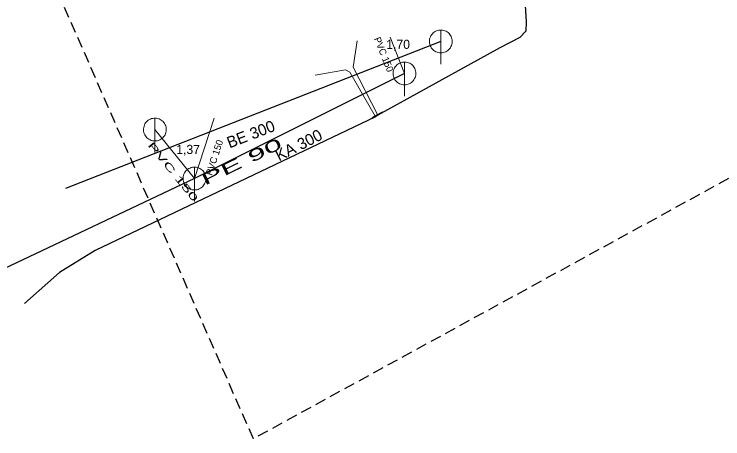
# Model space of a CAD drawing. Extents: x -693324 to -693034, y -967499 to -967236.
# Drawn here: x -693289.5 to -693227.3, y -967499.4 to -967462.2 of the extents above; entities that cross this region are included whole.
import ezdxf

# ---------------------------------------------------------------- set-up
doc = ezdxf.new("R2010")
doc.units = 0
doc.header["$LTSCALE"] = 0.32
doc.linetypes.add('MEDIUM_DASHED', pattern=[4.5, 3, -1.5])
doc.layers.add('1', color=7, linetype='Continuous')
for name, color, linetype, lineweight in [('11', 7, 'Continuous', 13), ('13', 7, 'Continuous', 13), ('14', 7, 'Continuous', 13), ('17', 7, 'Continuous', 25), ('22', 7, 'Continuous', 13), ('34', 7, 'Continuous', 13), ('63', 7, 'MEDIUM_DASHED', 25)]:
    doc.layers.add(name, color=color, linetype=linetype, lineweight=lineweight)

msp = doc.modelspace()

# ---------------------------------------------------------------- linework, layer by layer
at = {"layer": '11'}
for p, q in [((-693256.48, -967464.162), (-693255.221, -967467.353)), ((-693271.923, -967471.278), (-693273.644, -967476.568)), ((-693277.114, -967472.274), (-693273.644, -967476.568))]:
    msp.add_line(p, q, dxfattribs=at)
at = {"layer": '13'}
for points in [[(-693257.581, -967470.955), (-693259.737, -967466.818), (-693259.377, -967464.487)], [(-693257.793, -967471.099), (-693260.022, -967467.23), (-693260.386, -967467.035), (-693263.063, -967467.511)]]:
    msp.add_lwpolyline(points, dxfattribs=at)
at = {"layer": '14', "lineweight": 25}
for p, q in [((-693252.032, -967464.546), (-693284.967, -967477.43)), ((-693255.221, -967467.353), (-693273.644, -967476.568)), ((-693273.644, -967476.568), (-693294.817, -967486.566))]:
    msp.add_line(p, q, dxfattribs=at)
at = {"layer": '14'}
for p, q in [((-693257.767, -967471.145), (-693257.793, -967471.099)), ((-693257.557, -967471.002), (-693257.581, -967470.955))]:
    msp.add_line(p, q, dxfattribs=at)
at = {"layer": '17'}
msp.add_lwpolyline([(-693247.245, -967444.625), (-693244.666, -967460.901), (-693244.541, -967462.822), (-693244.585, -967463.638), (-693245.103, -967464.195), (-693246.853, -967465.098), (-693257.557, -967471.002), (-693257.767, -967471.145), (-693282.342, -967482.884), (-693285.493, -967484.813), (-693288.565, -967487.522)], dxfattribs=at)
at = {"layer": '22'}
for p, q in [((-693252.032, -967466.546), (-693252.031, -967463.546)), ((-693255.221, -967469.353), (-693255.22, -967466.353)), ((-693277.114, -967474.274), (-693277.113, -967471.274)), ((-693273.644, -967478.568), (-693273.643, -967475.568))]:
    msp.add_line(p, q, dxfattribs=at)
for points in [[(-693251.032, -967464.546), (-693251.037, -967464.437), (-693251.055, -967464.329), (-693251.085, -967464.223), (-693251.125, -967464.122), (-693251.177, -967464.025), (-693251.239, -967463.935), (-693251.311, -967463.852), (-693251.391, -967463.778), (-693251.479, -967463.712), (-693251.573, -967463.657), (-693251.673, -967463.612), (-693251.778, -967463.579), (-693251.885, -967463.557), (-693251.994, -967463.547), (-693252.104, -967463.549), (-693252.212, -967463.563), (-693252.319, -967463.588), (-693252.422, -967463.625), (-693252.52, -967463.674), (-693252.612, -967463.732), (-693252.698, -967463.801), (-693252.775, -967463.878), (-693252.844, -967463.964), (-693252.903, -967464.056), (-693252.951, -967464.154), (-693252.988, -967464.257), (-693253.014, -967464.364), (-693253.028, -967464.472), (-693253.031, -967464.582), (-693253.021, -967464.691), (-693253, -967464.798), (-693252.966, -967464.902), (-693252.922, -967465.002), (-693252.867, -967465.097), (-693252.801, -967465.185), (-693252.727, -967465.265), (-693252.644, -967465.337), (-693252.554, -967465.399), (-693252.458, -967465.451), (-693252.356, -967465.492), (-693252.251, -967465.522), (-693252.143, -967465.54), (-693252.033, -967465.546), (-693251.924, -967465.54), (-693251.816, -967465.522), (-693251.711, -967465.493), (-693251.609, -967465.452), (-693251.512, -967465.4), (-693251.422, -967465.338), (-693251.339, -967465.267), (-693251.264, -967465.187), (-693251.199, -967465.099), (-693251.143, -967465.005), (-693251.099, -967464.905), (-693251.065, -967464.801), (-693251.043, -967464.693), (-693251.033, -967464.584)], [(-693254.221, -967467.353), (-693254.226, -967467.244), (-693254.244, -967467.136), (-693254.274, -967467.03), (-693254.314, -967466.929), (-693254.366, -967466.832), (-693254.428, -967466.742), (-693254.5, -967466.659), (-693254.58, -967466.585), (-693254.668, -967466.519), (-693254.762, -967466.464), (-693254.862, -967466.419), (-693254.967, -967466.386), (-693255.074, -967466.364), (-693255.183, -967466.354), (-693255.293, -967466.356), (-693255.401, -967466.37), (-693255.508, -967466.395), (-693255.611, -967466.432), (-693255.709, -967466.481), (-693255.801, -967466.539), (-693255.887, -967466.608), (-693255.964, -967466.685), (-693256.033, -967466.771), (-693256.092, -967466.863), (-693256.14, -967466.961), (-693256.177, -967467.064), (-693256.203, -967467.171), (-693256.217, -967467.279), (-693256.22, -967467.389), (-693256.21, -967467.498), (-693256.189, -967467.605), (-693256.155, -967467.709), (-693256.111, -967467.809), (-693256.056, -967467.904), (-693255.99, -967467.992), (-693255.916, -967468.072), (-693255.833, -967468.144), (-693255.743, -967468.206), (-693255.647, -967468.258), (-693255.545, -967468.299), (-693255.44, -967468.329), (-693255.332, -967468.347), (-693255.222, -967468.353), (-693255.113, -967468.347), (-693255.005, -967468.329), (-693254.9, -967468.3), (-693254.798, -967468.259), (-693254.701, -967468.207), (-693254.611, -967468.145), (-693254.528, -967468.074), (-693254.453, -967467.994), (-693254.388, -967467.906), (-693254.332, -967467.812), (-693254.288, -967467.712), (-693254.254, -967467.608), (-693254.232, -967467.5), (-693254.222, -967467.391)], [(-693276.114, -967472.274), (-693276.119, -967472.165), (-693276.137, -967472.057), (-693276.167, -967471.951), (-693276.207, -967471.85), (-693276.259, -967471.753), (-693276.321, -967471.663), (-693276.393, -967471.58), (-693276.473, -967471.506), (-693276.561, -967471.44), (-693276.655, -967471.385), (-693276.755, -967471.34), (-693276.86, -967471.307), (-693276.967, -967471.285), (-693277.076, -967471.275), (-693277.186, -967471.277), (-693277.294, -967471.291), (-693277.401, -967471.316), (-693277.504, -967471.353), (-693277.602, -967471.402), (-693277.694, -967471.46), (-693277.78, -967471.529), (-693277.857, -967471.606), (-693277.926, -967471.692), (-693277.985, -967471.784), (-693278.033, -967471.882), (-693278.07, -967471.985), (-693278.096, -967472.092), (-693278.11, -967472.2), (-693278.113, -967472.31), (-693278.103, -967472.419), (-693278.082, -967472.526), (-693278.048, -967472.63), (-693278.004, -967472.73), (-693277.949, -967472.825), (-693277.883, -967472.913), (-693277.809, -967472.993), (-693277.726, -967473.065), (-693277.636, -967473.127), (-693277.54, -967473.179), (-693277.438, -967473.22), (-693277.333, -967473.25), (-693277.225, -967473.268), (-693277.115, -967473.274), (-693277.006, -967473.268), (-693276.898, -967473.25), (-693276.793, -967473.221), (-693276.691, -967473.18), (-693276.594, -967473.128), (-693276.504, -967473.066), (-693276.421, -967472.995), (-693276.346, -967472.915), (-693276.281, -967472.827), (-693276.225, -967472.733), (-693276.181, -967472.633), (-693276.147, -967472.529), (-693276.125, -967472.421), (-693276.115, -967472.312)], [(-693272.644, -967476.568), (-693272.649, -967476.459), (-693272.667, -967476.351), (-693272.697, -967476.245), (-693272.737, -967476.144), (-693272.789, -967476.047), (-693272.851, -967475.957), (-693272.923, -967475.874), (-693273.003, -967475.8), (-693273.091, -967475.734), (-693273.185, -967475.679), (-693273.285, -967475.634), (-693273.39, -967475.601), (-693273.497, -967475.579), (-693273.606, -967475.569), (-693273.716, -967475.571), (-693273.824, -967475.585), (-693273.931, -967475.61), (-693274.034, -967475.647), (-693274.132, -967475.696), (-693274.224, -967475.754), (-693274.31, -967475.823), (-693274.387, -967475.9), (-693274.456, -967475.986), (-693274.515, -967476.078), (-693274.563, -967476.176), (-693274.6, -967476.279), (-693274.626, -967476.386), (-693274.64, -967476.494), (-693274.643, -967476.604), (-693274.633, -967476.713), (-693274.612, -967476.82), (-693274.578, -967476.924), (-693274.534, -967477.024), (-693274.479, -967477.119), (-693274.413, -967477.207), (-693274.339, -967477.287), (-693274.256, -967477.359), (-693274.166, -967477.421), (-693274.07, -967477.473), (-693273.968, -967477.514), (-693273.863, -967477.544), (-693273.755, -967477.562), (-693273.645, -967477.568), (-693273.536, -967477.562), (-693273.428, -967477.544), (-693273.323, -967477.515), (-693273.221, -967477.474), (-693273.124, -967477.422), (-693273.034, -967477.36), (-693272.951, -967477.289), (-693272.876, -967477.209), (-693272.811, -967477.121), (-693272.755, -967477.027), (-693272.711, -967476.927), (-693272.677, -967476.823), (-693272.655, -967476.715), (-693272.645, -967476.606)]]:
    msp.add_lwpolyline(points, close=True, dxfattribs=at)
at = {"layer": '34'}
for p, q in [((-693258.225, -967471.349), (-693257.359, -967470.849)), ((-693258.024, -967471.186), (-693257.137, -967470.724))]:
    msp.add_line(p, q, dxfattribs=at)
at = {"layer": '63'}
msp.add_lwpolyline([(-693215.442, -967470.355), (-693268.475, -967499.384), (-693268.475, -967499.384), (-693301.969, -967422.904), (-693301.969, -967422.904), (-693282.431, -967353.124), (-693282.431, -967353.124), (-693315.367, -967297.3), (-693315.367, -967297.3), (-693271.824, -967262.689), (-693271.824, -967262.689), (-693150.127, -967236.451), (-693150.127, -967236.451), (-693034.013, -967255.99), (-693034.013, -967255.99), (-693048.527, -967323.537), (-693048.527, -967323.537), (-693120.541, -967319.63), (-693120.541, -967319.63), (-693193.67, -967351.449), (-693193.67, -967351.449), (-693214.325, -967418.997), (-693214.325, -967418.997)], close=True, dxfattribs=at)

# ---------------------------------------------------------------- texts
at = {"layer": '1'}
for s, height, rotation, p in [('PVC 150 ', 0.6, 292, (-693257.915, -967464.313)), ('BE 300', 1, 21, (-693270.569, -967473.929)), ('KA 300', 1, 27, (-693266.227, -967475.077)), ('PVC 150 ', 0.6, 72, (-693272.109, -967476.35))]:
    msp.add_text(s, height=height, rotation=rotation, dxfattribs=at).set_placement(p)
for s, p in [('1,70', (-693256.821, -967465.2)), ('1,37', (-693275.243, -967474.415))]:
    msp.add_text(s, height=0.8, dxfattribs=at).set_placement(p)
for s, height, rotation, width, p in [('PVC 150 ', 0.6, 309, 2, (-693277.781, -967473.662)), ('PE 90 ', 1, 26, 2.1, (-693272.734, -967477.202))]:
    msp.add_text(s, height=height, rotation=rotation, dxfattribs=dict(at, width=width)).set_placement(p)

doc.saveas('drawing.dxf')
